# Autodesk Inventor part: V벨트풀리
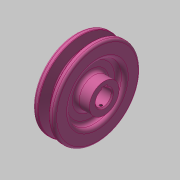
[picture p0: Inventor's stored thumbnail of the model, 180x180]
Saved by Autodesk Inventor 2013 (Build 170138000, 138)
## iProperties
Created: 2015-11
Part Number: V벨트풀리
Material: 강철, 탄소
Document SubType Name: Modeling
Designer: mduedu
Density: 1 g/cm^3
Author: mduedu
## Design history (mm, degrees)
sketch "스케치1"
  geometry: L1 (-9.5, 0)-(9.5, 0); L2 (0, 0)-(0, 37.7); L3 (-4.825, 37.7)-(-9.5, 37.7); L4 (-9.5, 37.7)-(-9.5, 0); L5 (0, 28.7)-(-2.074, 28.7); L6 (-2.074, 28.7)-(-4.825, 37.7); L7 (4.825, 37.7)-(9.5, 37.7); L8 (9.5, 37.7)-(9.5, 0); L9 (0, 28.7)-(2.074, 28.7); L10 (2.074, 28.7)-(4.825, 37.7); L11 (-9.5, 35)-(9.5, 35); 3 further points
  constraints: 22 end point, 7 point on line, 4 perpendicular, 3 symmetric about line, 1 coincident, 1 horizontal, 1 horizontal alignment, 1 midpoint, 1 vertical
  dimensions: "d0" = 19 distance of L1.start L1.end; "d2" = 75.4 diameter of L2.end L1 (derived); "d3" = 34 deg angle of L10 L6; "d4" = 6.3 distance between parallel lines of L11 L9; "d5" = 2.7 distance between parallel lines of L7 L11; "d6" = 8 distance of point (4, 35) point (-4, 35); "d7" = 70 diameter of L11 L1
revolve "회전1" sketch "스케치1" stored, may be unused: angle "d8" = 90 deg
sketch "스케치2"
  geometry: C1 r 24 at (0, 0); C2 r 13 at (0, 0); 1 further point
  constraints: 2 centre point, 2 coincident
  dimensions: "d9" = 48 diameter of C1; "d10" = 26 diameter of C2
extrude "돌출1" cut sketch "스케치2" distance "d11" = 6; taper "d12" = 0 deg
extrude "돌출3" join sketch "스케치2" distance "d37" = 6; taper "d38" = 0 deg
fillet "모깎기1" dims "d13" = 3
fillet "모깎기2" dims "d14" = 3
fillet "모깎기3" dims "d15" = 1, "d16" = 0.5, "d17" = 2
hole "구멍1" diameter "d20" = 14; stored, may be unused: countersink angle "d24" = 90 deg, drill point angle "d26" = 118 deg; dims "d21" = 6, "d22" = 4, "d23" = 2, "d25" = 8, "d61" = 10, "d62" = 10
sketch "스케치3"
  geometry: L1 (-2.5, 0)-(2.5, 0); L2 (2.5, 0)-(2.5, 9.3); L3 (2.5, 9.3)-(-2.5, 9.3); L4 (-2.5, 9.3)-(-2.5, 0); 2 further points
  constraints: 8 end point, 2 parallel, 1 coincident, 1 horizontal, 1 midpoint, 1 perpendicular
  dimensions: "d27" = 5 distance of L2.end L3.end; "d29" = 9.3 distance of L3.end L1.start
extrude "돌출2" cut sketch "스케치3" stored distance "d30" = 6; taper "d31" = 0 deg
chamfer "모따기1" distance "d32" = 1; stored, may be unused: second distance "d33" = 2, angle "d34" = 45 deg
node "작업 평면1"
sketch "스케치4"
  geometry: L1 (19, -27)-(19, 27) reference; 2 further points
  constraints: 1 horizontal alignment
  dimensions: "d52" = 22 distance from line of L1 point (-3, 0)
hole "구멍2" sketch "스케치4" at (-3, 0) diameter "d42" = 2.459; stored, may be unused: countersink angle "d46" = 90 deg, drill point angle "d48" = 118 deg; dims "d43" = 6, "d44" = 4, "d45" = 2, "d47" = 8
chamfer "모따기3" distance "d58" = 1; stored, may be unused: second distance "d59" = 2, angle "d60" = 45 deg
node "솔리드1"
mirror "대칭1"
